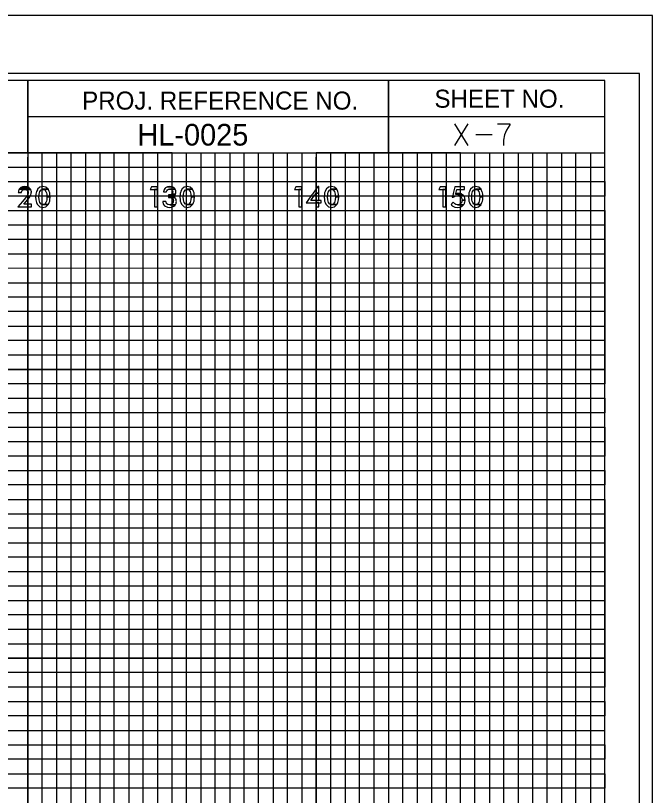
# Model space of a CAD drawing. Extents: x -13 to 323, y -5 to 1431.
# Drawn here: x 279.2 to 323.3, y 1260.5 to 1314.5 of the extents above; entities that cross this region are included whole.
import ezdxf

# ---------------------------------------------------------------- set-up
doc = ezdxf.new("R2010")
doc.units = 0
for name, color, linetype in [('Prop XS Offset Labels', 7, 'Continuous'), ('Prop XS Project Number', 7, 'Continuous'), ('Prop XS Sheet Number', 7, 'Continuous'), ('Sheet Cross Section CELL', 7, 'Continuous'), ('Sheet Cross Section Grid Major CELL', 7, 'Continuous'), ('Sheet Cross Section Grid Middle CELL', 7, 'Continuous'), ('Sheet Cross Section Grid Minor 1 CELL', 7, 'Continuous'), ('Sheet Cross Section Grid Minor 2 CELL', 7, 'Continuous'), ('Sheet Cutting Line CELL', 7, 'Continuous'), ('Sheet DOT Grid CELL', 7, 'Continuous'), ('Sheet Plot Border Inside CELL', 7, 'Continuous'), ('Sheet Plot Border Outside CELL', 7, 'Continuous')]:
    doc.layers.add(name, color=color, linetype=linetype)

msp = doc.modelspace()

# ---------------------------------------------------------------- linework, layer by layer
at = {"layer": 'Prop XS Offset Labels'}
for points in [[(279.507, 1302.583), (279.41, 1302.479), (280.197, 1302.479), (280.108, 1302.583)], [(279.512, 1302.585), (279.507, 1302.583), (280.108, 1302.583), (280.106, 1302.585), (279.974, 1302.645), (279.958, 1302.652), (279.794, 1302.668), (279.794, 1302.668), (279.685, 1302.652), (279.637, 1302.645)], [(280.851, 1301.255), (281.051, 1301.214), (281.245, 1301.255), (281.256, 1301.257), (281.422, 1301.409), (281.048, 1301.409), (281.038, 1301.411), (281.033, 1301.413), (280.928, 1301.442), (280.841, 1301.555), (280.841, 1301.556), (280.841, 1301.556), (280.813, 1301.657), (280.813, 1301.659), (280.793, 1301.732), (280.792, 1301.736), (280.774, 1301.939), (280.774, 1301.941), (280.774, 1301.943), (280.792, 1302.145), (280.812, 1302.222), (280.813, 1302.224), (280.839, 1302.322), (280.84, 1302.325), (280.928, 1302.44), (281.041, 1302.469), (281.045, 1302.47), (281.055, 1302.473), (281.425, 1302.473), (281.262, 1302.622), (281.254, 1302.624), (281.053, 1302.668), (281.053, 1302.668), (280.845, 1302.624), (280.843, 1302.622), (280.681, 1302.473), (280.678, 1302.47), (280.678, 1302.469), (280.665, 1302.44), (280.618, 1302.325), (280.617, 1302.322), (280.577, 1302.224), (280.576, 1302.222), (280.568, 1302.145), (280.547, 1301.943), (280.547, 1301.941), (280.547, 1301.939), (280.567, 1301.736), (280.567, 1301.732), (280.575, 1301.659), (280.575, 1301.657), (280.616, 1301.556), (280.617, 1301.555), (280.663, 1301.442), (280.675, 1301.413), (280.676, 1301.411), (280.679, 1301.409), (280.848, 1301.257)], [(288.581, 1302.641), (288.492, 1302.459), (288.99, 1302.459), (288.99, 1302.641)], [(289.42, 1302.315), (289.418, 1302.297), (289.626, 1302.297), (289.627, 1302.315), (289.639, 1302.365), (289.64, 1302.372), (289.641, 1302.373), (289.683, 1302.433), (289.688, 1302.436), (289.696, 1302.44), (289.748, 1302.47), (289.785, 1302.476), (289.795, 1302.478), (289.835, 1302.485), (290.217, 1302.485), (290.165, 1302.561), (290.129, 1302.582), (290.128, 1302.582), (290.022, 1302.644), (289.982, 1302.65), (289.69, 1302.65), (289.678, 1302.644), (289.553, 1302.582), (289.536, 1302.561), (289.471, 1302.485), (289.466, 1302.478), (289.465, 1302.476), (289.463, 1302.47), (289.452, 1302.44), (289.45, 1302.436), (289.449, 1302.433), (289.428, 1302.373), (289.427, 1302.372), (289.425, 1302.365)], [(289.853, 1302.668), (289.69, 1302.65), (289.982, 1302.65)], [(290.007, 1302.155), (289.988, 1302.131), (290.23, 1302.131), (290.246, 1302.155), (290.254, 1302.201), (290.271, 1302.289), (290.272, 1302.295), (290.272, 1302.297), (290.269, 1302.315), (290.26, 1302.365), (290.259, 1302.372), (290.259, 1302.373), (290.259, 1302.373), (290.249, 1302.433), (290.248, 1302.436), (290.248, 1302.44), (290.227, 1302.47), (290.223, 1302.476), (290.222, 1302.478), (290.217, 1302.485), (289.835, 1302.485), (289.901, 1302.478), (289.919, 1302.476), (289.931, 1302.47), (289.986, 1302.44), (289.995, 1302.436), (289.997, 1302.433), (290.04, 1302.373), (290.04, 1302.372), (290.042, 1302.365), (290.051, 1302.315), (290.054, 1302.297), (290.055, 1302.295), (290.056, 1302.289), (290.041, 1302.201)], [(290.851, 1301.255), (291.051, 1301.214), (291.245, 1301.255), (291.256, 1301.257), (291.422, 1301.409), (291.048, 1301.409), (291.038, 1301.411), (291.033, 1301.413), (290.928, 1301.442), (290.841, 1301.555), (290.841, 1301.556), (290.841, 1301.556), (290.813, 1301.657), (290.813, 1301.659), (290.793, 1301.732), (290.792, 1301.736), (290.774, 1301.939), (290.774, 1301.941), (290.774, 1301.943), (290.792, 1302.145), (290.812, 1302.222), (290.813, 1302.224), (290.839, 1302.322), (290.84, 1302.325), (290.928, 1302.44), (291.041, 1302.469), (291.045, 1302.47), (291.055, 1302.473), (291.425, 1302.473), (291.262, 1302.622), (291.254, 1302.624), (291.053, 1302.668), (291.053, 1302.668), (290.845, 1302.624), (290.843, 1302.622), (290.681, 1302.473), (290.678, 1302.47), (290.678, 1302.469), (290.665, 1302.44), (290.618, 1302.325), (290.617, 1302.322), (290.577, 1302.224), (290.576, 1302.222), (290.568, 1302.145), (290.547, 1301.943), (290.547, 1301.941), (290.547, 1301.939), (290.567, 1301.736), (290.567, 1301.732), (290.575, 1301.659), (290.575, 1301.657), (290.616, 1301.556), (290.617, 1301.555), (290.663, 1301.442), (290.675, 1301.413), (290.676, 1301.411), (290.679, 1301.409), (290.848, 1301.257)], [(298.581, 1302.641), (298.492, 1302.459), (298.99, 1302.459), (298.99, 1302.641)], [(299.411, 1301.693), (299.297, 1301.534), (300.35, 1301.534), (300.35, 1301.693), (299.618, 1301.693), (299.878, 1302.059), (299.935, 1302.139), (299.977, 1302.199), (300.179, 1302.199), (300.179, 1302.668), (300.114, 1302.668), (299.775, 1302.199), (299.733, 1302.139), (299.675, 1302.059)], [(300.851, 1301.255), (301.051, 1301.214), (301.245, 1301.255), (301.256, 1301.257), (301.422, 1301.409), (301.048, 1301.409), (301.038, 1301.411), (301.033, 1301.413), (300.928, 1301.442), (300.841, 1301.555), (300.841, 1301.556), (300.841, 1301.556), (300.813, 1301.657), (300.813, 1301.659), (300.793, 1301.732), (300.792, 1301.736), (300.774, 1301.939), (300.774, 1301.941), (300.774, 1301.943), (300.792, 1302.145), (300.812, 1302.222), (300.813, 1302.224), (300.839, 1302.322), (300.84, 1302.325), (300.928, 1302.44), (301.041, 1302.469), (301.045, 1302.47), (301.055, 1302.473), (301.425, 1302.473), (301.262, 1302.622), (301.254, 1302.624), (301.053, 1302.668), (301.053, 1302.668), (300.845, 1302.624), (300.843, 1302.622), (300.681, 1302.473), (300.678, 1302.47), (300.678, 1302.469), (300.665, 1302.44), (300.618, 1302.325), (300.617, 1302.322), (300.577, 1302.224), (300.576, 1302.222), (300.568, 1302.145), (300.547, 1301.943), (300.547, 1301.941), (300.547, 1301.939), (300.567, 1301.736), (300.567, 1301.732), (300.575, 1301.659), (300.575, 1301.657), (300.616, 1301.556), (300.617, 1301.555), (300.663, 1301.442), (300.675, 1301.413), (300.676, 1301.411), (300.679, 1301.409), (300.848, 1301.257)], [(308.581, 1302.641), (308.492, 1302.459), (308.99, 1302.459), (308.99, 1302.641)], [(309.427, 1301.94), (309.424, 1301.928), (309.495, 1301.928), (309.508, 1301.94), (309.524, 1301.954), (309.595, 1301.997), (309.627, 1302.007), (309.697, 1302.029), (309.811, 1302.035), (310.219, 1302.035), (310.211, 1302.05), (310.076, 1302.145), (309.655, 1302.145), (309.658, 1302.158), (309.658, 1302.158), (309.663, 1302.178), (309.738, 1302.456), (310.263, 1302.456), (310.263, 1302.641), (309.6, 1302.641), (309.554, 1302.456), (309.486, 1302.178), (309.481, 1302.158), (309.478, 1302.145), (309.454, 1302.05), (309.451, 1302.035), (309.449, 1302.029), (309.444, 1302.007), (309.441, 1301.997), (309.431, 1301.954)], [(310.851, 1301.255), (311.051, 1301.214), (311.245, 1301.255), (311.256, 1301.257), (311.422, 1301.409), (311.048, 1301.409), (311.038, 1301.411), (311.033, 1301.413), (310.928, 1301.442), (310.841, 1301.555), (310.841, 1301.556), (310.841, 1301.556), (310.813, 1301.657), (310.813, 1301.659), (310.793, 1301.732), (310.792, 1301.736), (310.774, 1301.939), (310.774, 1301.941), (310.774, 1301.943), (310.792, 1302.145), (310.812, 1302.222), (310.813, 1302.224), (310.839, 1302.322), (310.84, 1302.325), (310.928, 1302.44), (311.041, 1302.469), (311.045, 1302.47), (311.055, 1302.473), (311.425, 1302.473), (311.262, 1302.622), (311.254, 1302.624), (311.053, 1302.668), (311.053, 1302.668), (310.845, 1302.624), (310.843, 1302.622), (310.681, 1302.473), (310.678, 1302.47), (310.678, 1302.469), (310.665, 1302.44), (310.618, 1302.325), (310.617, 1302.322), (310.577, 1302.224), (310.576, 1302.222), (310.568, 1302.145), (310.547, 1301.943), (310.547, 1301.941), (310.547, 1301.939), (310.567, 1301.736), (310.567, 1301.732), (310.575, 1301.659), (310.575, 1301.657), (310.616, 1301.556), (310.617, 1301.555), (310.663, 1301.442), (310.675, 1301.413), (310.676, 1301.411), (310.679, 1301.409), (310.848, 1301.257)], [(279.465, 1301.432), (279.313, 1301.25), (280.253, 1301.25), (280.253, 1301.432), (279.719, 1301.432), (279.898, 1301.638), (280.095, 1301.879), (280.097, 1301.881), (280.208, 1302.069), (280.208, 1302.069), (280.211, 1302.074), (280.235, 1302.193), (280.247, 1302.254), (280.252, 1302.279), (280.25, 1302.29), (280.249, 1302.293), (280.236, 1302.354), (280.235, 1302.36), (280.233, 1302.37), (280.222, 1302.421), (280.222, 1302.421), (280.219, 1302.435), (280.213, 1302.461), (280.211, 1302.464), (280.207, 1302.468), (279.839, 1302.468), (279.85, 1302.464), (279.858, 1302.461), (279.933, 1302.435), (279.946, 1302.421), (279.996, 1302.37), (280, 1302.36), (280.002, 1302.354), (280.022, 1302.293), (280.022, 1302.29), (280.022, 1302.279), (280.022, 1302.254), (280.021, 1302.193), (279.973, 1302.074), (279.972, 1302.069), (279.839, 1301.881), (279.838, 1301.879), (279.637, 1301.638)], [(279.349, 1302.279), (279.347, 1302.254), (279.567, 1302.254), (279.569, 1302.279), (279.57, 1302.29), (279.571, 1302.293), (279.593, 1302.354), (279.598, 1302.36), (279.606, 1302.37), (279.645, 1302.421), (279.673, 1302.435), (279.725, 1302.461), (279.73, 1302.464), (279.839, 1302.468), (280.207, 1302.468), (280.197, 1302.479), (279.41, 1302.479), (279.405, 1302.468), (279.403, 1302.464), (279.402, 1302.461), (279.39, 1302.435), (279.384, 1302.421), (279.361, 1302.37), (279.357, 1302.36), (279.356, 1302.354), (279.35, 1302.293), (279.35, 1302.29)], [(281.058, 1301.411), (281.048, 1301.409), (281.422, 1301.409), (281.425, 1301.411), (281.426, 1301.413), (281.438, 1301.442), (281.485, 1301.555), (281.485, 1301.556), (281.527, 1301.657), (281.528, 1301.659), (281.535, 1301.732), (281.535, 1301.736), (281.555, 1301.939), (281.556, 1301.941), (281.555, 1301.943), (281.328, 1301.943), (281.328, 1301.941), (281.328, 1301.939), (281.312, 1301.736), (281.312, 1301.732), (281.292, 1301.659), (281.291, 1301.657), (281.264, 1301.556), (281.263, 1301.555), (281.175, 1301.442), (281.063, 1301.413)], [(281.312, 1302.145), (281.328, 1301.943), (281.555, 1301.943), (281.536, 1302.145), (281.528, 1302.222), (281.528, 1302.224), (281.527, 1302.224), (281.488, 1302.322), (281.488, 1302.322), (281.487, 1302.325), (281.441, 1302.44), (281.44, 1302.44), (281.429, 1302.469), (281.428, 1302.47), (281.425, 1302.473), (281.055, 1302.473), (281.065, 1302.47), (281.068, 1302.469), (281.175, 1302.44), (281.262, 1302.325), (281.265, 1302.322), (281.291, 1302.224), (281.291, 1302.222)], [(288.781, 1302.459), (288.781, 1301.25), (288.99, 1301.25), (288.99, 1302.459)], [(289.765, 1301.956), (289.765, 1301.9), (290.194, 1301.9), (290.119, 1301.956), (290.029, 1301.983), (290.095, 1302), (290.181, 1302.053), (290.2, 1302.084), (290.201, 1302.085), (290.207, 1302.095), (289.915, 1302.095), (289.83, 1302.085), (289.765, 1302.084), (289.765, 1302.053), (289.765, 1302), (289.765, 1301.983)], [(289.988, 1302.131), (289.915, 1302.095), (290.207, 1302.095), (290.23, 1302.131)], [(291.058, 1301.411), (291.048, 1301.409), (291.422, 1301.409), (291.425, 1301.411), (291.426, 1301.413), (291.438, 1301.442), (291.485, 1301.555), (291.485, 1301.556), (291.527, 1301.657), (291.528, 1301.659), (291.535, 1301.732), (291.535, 1301.736), (291.555, 1301.939), (291.556, 1301.941), (291.555, 1301.943), (291.328, 1301.943), (291.328, 1301.941), (291.328, 1301.939), (291.312, 1301.736), (291.312, 1301.732), (291.292, 1301.659), (291.291, 1301.657), (291.264, 1301.556), (291.263, 1301.555), (291.175, 1301.442), (291.063, 1301.413)], [(291.312, 1302.145), (291.328, 1301.943), (291.555, 1301.943), (291.536, 1302.145), (291.528, 1302.222), (291.528, 1302.224), (291.527, 1302.224), (291.488, 1302.322), (291.488, 1302.322), (291.487, 1302.325), (291.441, 1302.44), (291.44, 1302.44), (291.429, 1302.469), (291.428, 1302.47), (291.425, 1302.473), (291.055, 1302.473), (291.065, 1302.47), (291.068, 1302.469), (291.175, 1302.44), (291.262, 1302.325), (291.265, 1302.322), (291.291, 1302.224), (291.291, 1302.222)], [(298.781, 1302.459), (298.781, 1301.25), (298.99, 1301.25), (298.99, 1302.459)], [(299.97, 1302.059), (299.97, 1301.693), (300.179, 1301.693), (300.179, 1302.059), (300.179, 1302.139), (300.179, 1302.199), (299.977, 1302.199), (299.973, 1302.139)], [(301.058, 1301.411), (301.048, 1301.409), (301.422, 1301.409), (301.425, 1301.411), (301.426, 1301.413), (301.438, 1301.442), (301.485, 1301.555), (301.485, 1301.556), (301.527, 1301.657), (301.528, 1301.659), (301.535, 1301.732), (301.535, 1301.736), (301.555, 1301.939), (301.556, 1301.941), (301.555, 1301.943), (301.328, 1301.943), (301.328, 1301.941), (301.328, 1301.939), (301.312, 1301.736), (301.312, 1301.732), (301.292, 1301.659), (301.291, 1301.657), (301.264, 1301.556), (301.263, 1301.555), (301.175, 1301.442), (301.063, 1301.413)], [(301.312, 1302.145), (301.328, 1301.943), (301.555, 1301.943), (301.536, 1302.145), (301.528, 1302.222), (301.528, 1302.224), (301.527, 1302.224), (301.488, 1302.322), (301.488, 1302.322), (301.487, 1302.325), (301.441, 1302.44), (301.44, 1302.44), (301.429, 1302.469), (301.428, 1302.47), (301.425, 1302.473), (301.055, 1302.473), (301.065, 1302.47), (301.068, 1302.469), (301.175, 1302.44), (301.262, 1302.325), (301.265, 1302.322), (301.291, 1302.224), (301.291, 1302.222)], [(308.781, 1302.459), (308.781, 1301.25), (308.99, 1301.25), (308.99, 1302.459)], [(309.692, 1302.158), (309.655, 1302.145), (310.076, 1302.145), (310.058, 1302.158), (309.961, 1302.178), (309.75, 1302.178)], [(309.888, 1302.192), (309.75, 1302.178), (309.96, 1302.178), (309.888, 1302.192)], [(310.083, 1301.841), (310.105, 1301.721), (310.318, 1301.721), (310.307, 1301.841), (310.307, 1301.841), (310.303, 1301.881), (310.284, 1301.916), (310.278, 1301.928), (310.271, 1301.94), (310.263, 1301.954), (310.24, 1301.997), (310.235, 1302.007), (310.223, 1302.029), (310.219, 1302.035), (309.811, 1302.035), (309.838, 1302.029), (309.928, 1302.007), (309.942, 1301.997), (310.003, 1301.954), (310.024, 1301.94), (310.031, 1301.928), (310.038, 1301.916), (310.059, 1301.881)], [(311.058, 1301.411), (311.048, 1301.409), (311.422, 1301.409), (311.425, 1301.411), (311.426, 1301.413), (311.438, 1301.442), (311.485, 1301.555), (311.485, 1301.556), (311.527, 1301.657), (311.528, 1301.659), (311.535, 1301.732), (311.535, 1301.736), (311.555, 1301.939), (311.556, 1301.941), (311.555, 1301.943), (311.328, 1301.943), (311.328, 1301.941), (311.328, 1301.939), (311.312, 1301.736), (311.312, 1301.732), (311.292, 1301.659), (311.291, 1301.657), (311.264, 1301.556), (311.263, 1301.555), (311.175, 1301.442), (311.063, 1301.413)], [(311.312, 1302.145), (311.328, 1301.943), (311.555, 1301.943), (311.536, 1302.145), (311.528, 1302.222), (311.528, 1302.224), (311.527, 1302.224), (311.488, 1302.322), (311.488, 1302.322), (311.487, 1302.325), (311.441, 1302.44), (311.44, 1302.44), (311.429, 1302.469), (311.428, 1302.47), (311.425, 1302.473), (311.055, 1302.473), (311.065, 1302.47), (311.068, 1302.469), (311.175, 1302.44), (311.262, 1302.325), (311.265, 1302.322), (311.291, 1302.224), (311.291, 1302.222)], [(289.677, 1301.229), (289.854, 1301.214), (289.936, 1301.229), (290.042, 1301.248), (290.123, 1301.297), (290.187, 1301.336), (290.228, 1301.399), (290.229, 1301.401), (289.849, 1301.401), (289.72, 1301.416), (289.711, 1301.423), (289.639, 1301.471), (289.628, 1301.479), (289.626, 1301.482), (289.608, 1301.516), (289.584, 1301.562), (289.584, 1301.567), (289.58, 1301.62), (289.58, 1301.625), (289.361, 1301.625), (289.362, 1301.62), (289.369, 1301.567), (289.37, 1301.562), (289.377, 1301.516), (289.391, 1301.482), (289.392, 1301.479), (289.395, 1301.471), (289.415, 1301.423), (289.418, 1301.416), (289.425, 1301.401), (289.426, 1301.399), (289.49, 1301.336), (289.53, 1301.297), (289.635, 1301.248)], [(289.925, 1301.416), (289.849, 1301.401), (290.229, 1301.401), (290.239, 1301.416), (290.243, 1301.423), (290.243, 1301.423), (290.275, 1301.471), (290.277, 1301.479), (290.277, 1301.482), (290.283, 1301.516), (290.292, 1301.562), (290.293, 1301.567), (290.303, 1301.62), (290.297, 1301.662), (290.285, 1301.751), (290.283, 1301.763), (290.25, 1301.826), (290.223, 1301.877), (290.222, 1301.88), (290.197, 1301.898), (290.194, 1301.9), (289.81, 1301.9), (289.877, 1301.898), (289.951, 1301.88), (289.963, 1301.877), (290.033, 1301.826), (290.07, 1301.763), (290.077, 1301.751), (290.092, 1301.662), (290.088, 1301.62), (290.082, 1301.567), (290.08, 1301.562), (290.057, 1301.516), (290.039, 1301.482), (290.035, 1301.479), (290.025, 1301.471), (289.957, 1301.423)], [(299.97, 1301.534), (299.97, 1301.25), (300.179, 1301.25), (300.179, 1301.534)], [(309.626, 1301.233), (309.762, 1301.214), (309.959, 1301.233), (309.968, 1301.237), (310.091, 1301.297), (310.091, 1301.297), (310.141, 1301.321), (310.185, 1301.375), (310.204, 1301.399), (309.793, 1301.399), (309.683, 1301.418), (309.682, 1301.419), (309.679, 1301.42), (309.596, 1301.466), (309.586, 1301.477), (309.58, 1301.483), (309.58, 1301.483), (309.529, 1301.535), (309.497, 1301.585), (309.497, 1301.585), (309.451, 1301.535), (309.404, 1301.483), (309.399, 1301.477), (309.39, 1301.466), (309.348, 1301.42), (309.347, 1301.419), (309.348, 1301.418), (309.363, 1301.399), (309.382, 1301.375), (309.445, 1301.321), (309.474, 1301.297), (309.598, 1301.237)], [(309.424, 1301.928), (309.482, 1301.916), (309.495, 1301.928)], [(309.9, 1301.418), (309.793, 1301.399), (310.204, 1301.399), (310.22, 1301.418), (310.221, 1301.419), (310.222, 1301.42), (310.222, 1301.42), (310.259, 1301.466), (310.268, 1301.477), (310.27, 1301.483), (310.284, 1301.535), (310.299, 1301.59), (310.322, 1301.674), (310.318, 1301.721), (310.105, 1301.721), (310.097, 1301.674), (310.082, 1301.59), (310.047, 1301.535), (310.014, 1301.483), (310.004, 1301.477), (309.987, 1301.466), (309.913, 1301.42), (309.905, 1301.419)]]:
    msp.add_lwpolyline(points, close=True, dxfattribs=at)
at = {"layer": 'Prop XS Sheet Number'}
for p, q in [((309.575, 1307), (310.508, 1305.5)), ((310.508, 1307), (309.575, 1305.5)), ((311.063, 1306.256), (312.185, 1306.256))]:
    msp.add_line(p, q, dxfattribs=at)
for points in [[(312.551, 1307), (313.425, 1307), (313.425, 1306.941)], [(313.425, 1306.941), (313.177, 1306.563), (313.047, 1306.244), (312.988, 1305.878), (312.988, 1305.5)]]:
    msp.add_lwpolyline(points, dxfattribs=at)
at = {"layer": 'Sheet Cross Section CELL'}
for p, q in [((305, 1310), (305, 1305)), ((305, 1305), (305, 1310)), ((280, 1307.5), (280, 1305)), ((320, 1307.49), (280, 1307.49)), ((280, 1305), (320, 1305))]:
    msp.add_line(p, q, dxfattribs=at)
for points in [[(320, 1310), (0, 1310), (0, 1100), (320, 1100)], [(280, 1310), (260, 1310), (260, 1305.03), (280, 1305.03)], [(320, 1310), (280, 1310), (280, 1305), (320, 1305)]]:
    msp.add_lwpolyline(points, close=True, dxfattribs=at)
at = {"layer": 'Sheet Cross Section Grid Major CELL'}
for p, q in [((290, 1305), (280, 1305)), ((280, 1305), (280, 1100)), ((290, 1100), (290, 1305)), ((310, 1305), (300, 1305)), ((300, 1305), (300, 1100)), ((310, 1100), (310, 1305))]:
    msp.add_line(p, q, dxfattribs=at)
for points in [[(0, 1300), (320, 1300), (320, 1290), (0, 1290)], [(0, 1280), (320, 1280), (320, 1270), (0, 1270)]]:
    msp.add_lwpolyline(points, dxfattribs=at)
at = {"layer": 'Sheet Cross Section Grid Middle CELL'}
for points in [[(275, 1100), (275, 1305), (285, 1305), (285, 1100)], [(295, 1100), (295, 1305), (305, 1305), (305, 1100)], [(315, 1100), (315, 1305)], [(0, 1285), (320, 1285), (320, 1295), (0, 1295)], [(0, 1265), (320, 1265), (320, 1275), (0, 1275)]]:
    msp.add_lwpolyline(points, dxfattribs=at)
at = {"layer": 'Sheet Cross Section Grid Minor 1 CELL'}
msp.add_line((0, 1304), (320, 1304), dxfattribs=at)
for points in [[(0, 1303), (270, 1303), (320, 1303), (320, 1302), (0, 1302)], [(0, 1301), (320, 1301), (320, 1299), (0, 1299)], [(0, 1298), (320, 1298), (320, 1297), (0, 1296.98)], [(0, 1296), (320, 1296), (320, 1294), (0, 1294)], [(0, 1293), (320, 1293), (320, 1292), (0, 1292)], [(0, 1291), (320, 1291), (320, 1289), (0, 1289)], [(0, 1288), (320, 1288), (320, 1287), (0, 1287)], [(0, 1286), (320, 1286), (320, 1284), (0, 1284)], [(0, 1283), (320, 1283), (320, 1282), (0, 1282)], [(0, 1281), (320, 1281), (320, 1279), (0, 1279)], [(0, 1278), (320, 1278), (320, 1277), (0, 1277)], [(0, 1276), (320, 1276), (320, 1273.95), (320, 1273), (320, 1272), (0, 1272)], [(0, 1274), (320, 1274), (320, 1273), (0, 1273)], [(0, 1271), (320, 1271), (320, 1269), (0, 1269.03)], [(0, 1269.03), (320, 1269), (320, 1268), (0, 1268)], [(0, 1267), (320, 1267), (320, 1266), (0, 1266)], [(0, 1264), (320, 1264), (320, 1263), (0, 1263)], [(0, 1262), (320, 1262), (320, 1261), (0, 1261)]]:
    msp.add_lwpolyline(points, dxfattribs=at)
at = {"layer": 'Sheet Cross Section Grid Minor 2 CELL'}
for points in [[(280, 1100), (281, 1100), (281, 1305), (282, 1305), (282, 1100)], [(282, 1100), (283, 1100), (283, 1305), (284, 1305), (284, 1100)], [(285, 1100), (286, 1100), (286, 1305), (287, 1305), (287, 1100)], [(287, 1100), (288, 1100), (288, 1305), (289, 1305), (289, 1100)], [(290, 1100), (291, 1100), (291, 1305), (292, 1305), (292, 1100)], [(292, 1100), (293, 1100), (293, 1305), (294, 1305), (294, 1100)], [(295, 1100), (296, 1100), (296, 1305), (297, 1305), (297, 1100)], [(297, 1100), (298, 1100), (298, 1305), (299, 1305), (299, 1100)], [(300, 1100), (301, 1100), (301, 1305), (302, 1305), (302, 1100)], [(302, 1100), (303, 1100), (303, 1305), (304, 1305), (304, 1100)], [(305, 1100), (306, 1100), (306, 1305), (307, 1305), (307, 1100)], [(307, 1100), (308, 1100), (308, 1305), (309, 1305), (309, 1100)], [(310, 1100), (311, 1100), (311, 1305), (312, 1305), (312, 1100)], [(312, 1100), (313, 1100), (313, 1305), (314, 1305), (314, 1100)], [(315, 1100), (316, 1100), (316, 1305), (317, 1305), (317, 1100)], [(317, 1100), (318, 1100), (318, 1305), (319, 1305), (319, 1100)]]:
    msp.add_lwpolyline(points, dxfattribs=at)
at = {"layer": 'Sheet Cutting Line CELL'}
msp.add_line((323.3, 1314.5), (-13.4, 1314.5), dxfattribs=at)
at = {"layer": 'Sheet DOT Grid CELL'}
for p, q in [((280, 1100), (280, 1304.687)), ((290, 1100), (290, 1304.687)), ((300, 1100), (300, 1304.687)), ((310, 1100), (310, 1304.687)), ((0, 1300), (320, 1300)), ((0, 1290), (320, 1290)), ((0, 1280), (320, 1280)), ((0, 1270), (320, 1270))]:
    msp.add_line(p, q, dxfattribs=at)
at = {"layer": 'Sheet Plot Border Inside CELL'}
msp.add_lwpolyline([(-10.8, 1099.5), (322.4, 1099.5), (322.4, 1310.5), (-10.8, 1310.5)], close=True, dxfattribs=at)
at = {"layer": 'Sheet Plot Border Outside CELL'}
msp.add_lwpolyline([(-13.4, 1095.5), (323.3, 1095.5), (323.3, 1314.5), (-13.4, 1314.5)], close=True, dxfattribs=at)

# ---------------------------------------------------------------- texts
at = {"layer": 'Prop XS Project Number'}
msp.add_text('HL-0025', height=1.5, dxfattribs=at).set_placement((287.598, 1305.5))
at = {"layer": 'Sheet Cross Section CELL'}
for s, height, p in [('PROJ. REFERENCE NO.', 1.24998, (283.77, 1307.99)), ('SHEET NO.', 1.25, (308.19, 1308.12))]:
    msp.add_text(s, height=height, dxfattribs=at).set_placement(p)

doc.saveas('drawing.dxf')
